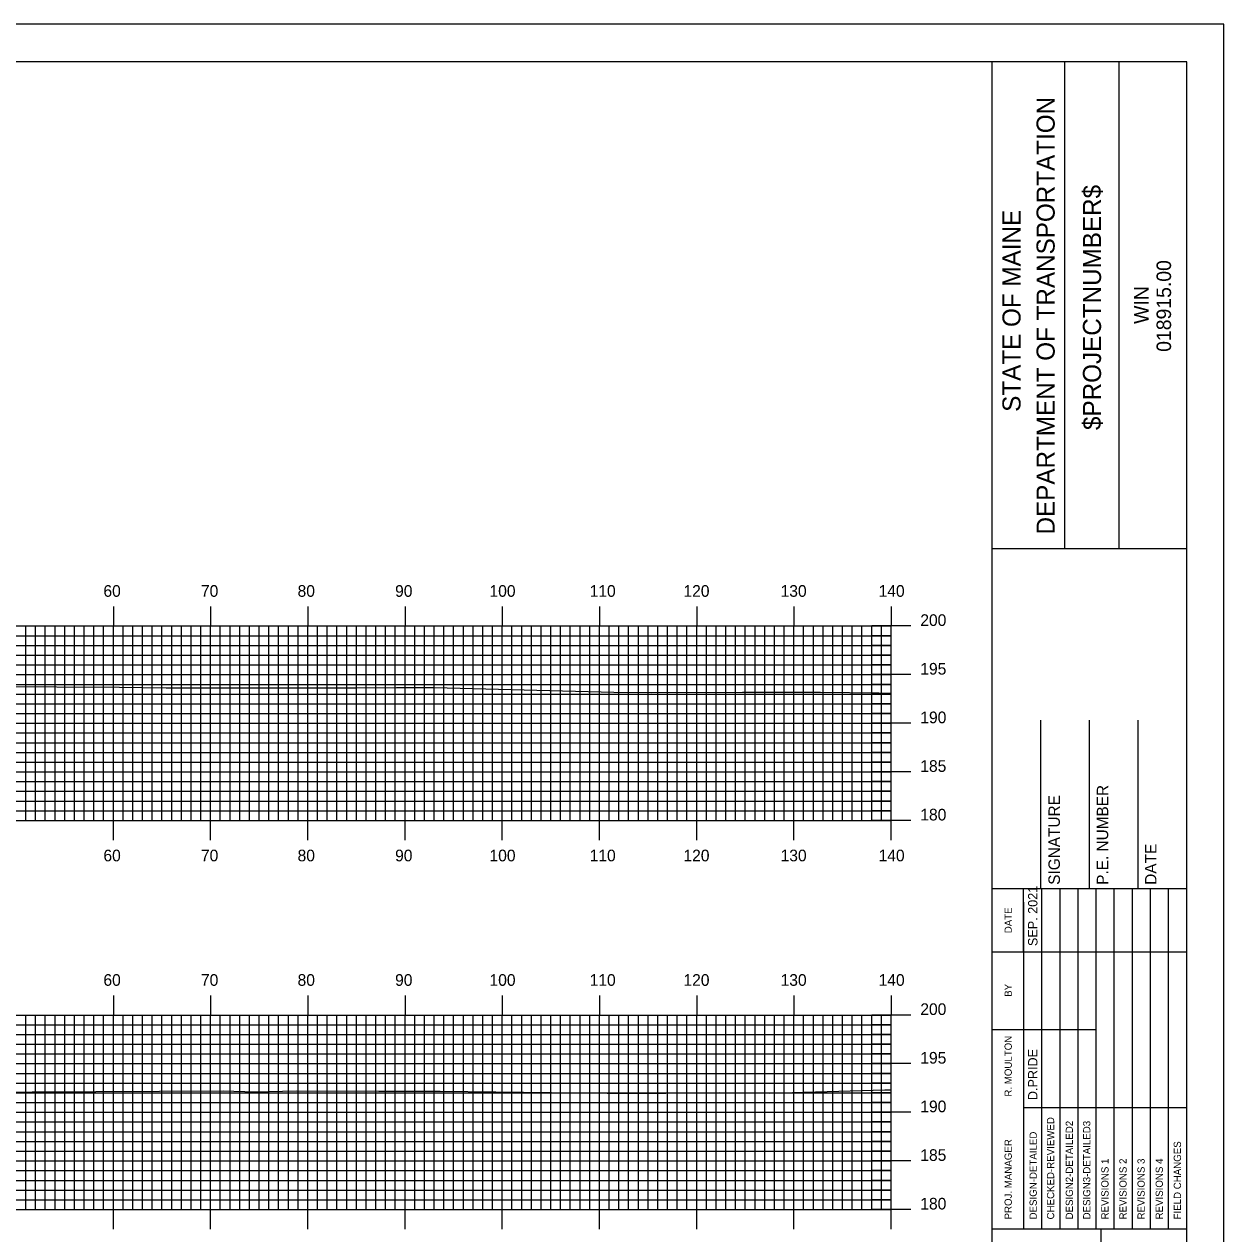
# Model space of a CAD drawing. Extents: x 1798781 to 1799124, y 442591 to 442811.
# Drawn here: x 1798997.8 to 1799121.2, y 442686.2 to 442810.5 of the extents above; entities that cross this region are included whole.
import ezdxf

# ---------------------------------------------------------------- set-up
doc = ezdxf.new("R2010")
doc.units = 0
for name, color, linetype in [('BORDER', 7, 'Continuous'), ('H_V ANNOTATION', 7, 'Continuous'), ('MAJOR', 7, 'Continuous'), ('MINOR', 7, 'Continuous'), ('PLOT BOUNDARY', 7, 'Continuous'), ('S_Roadway_Centerline', 7, 'Continuous')]:
    doc.layers.add(name, color=color, linetype=linetype)

msp = doc.modelspace()

# ---------------------------------------------------------------- linework, layer by layer
at = {"layer": 'BORDER'}
for p, q in [((1799097.38, 442596.67), (1799097.38, 442806.67)), ((1799104.84, 442756.66), (1799104.84, 442806.66)), ((1799110.43, 442756.66), (1799110.43, 442806.66)), ((1799097.39, 442756.65), (1799117.38, 442756.65)), ((1799102.38, 442721.67), (1799102.38, 442738.97)), ((1799107.38, 442721.67), (1799107.38, 442738.97)), ((1799112.38, 442721.67), (1799112.38, 442738.97)), ((1799097.38, 442721.67), (1799117.38, 442721.67)), ((1799097.38, 442686.67), (1799117.38, 442686.67)), ((1799108.57, 442616.67), (1799108.57, 442686.67))]:
    msp.add_line(p, q, dxfattribs=at)
msp.add_lwpolyline([(1798797.38, 442596.67), (1799117.38, 442596.67), (1799117.38, 442806.67), (1798797.38, 442806.67)], close=True, dxfattribs=at)
for points in [[(1799100.61, 442715.17), (1799100.61, 442721.67)], [(1799102.48, 442686.68), (1799102.48, 442721.67)], [(1799104.34, 442721.67), (1799104.34, 442686.68)], [(1799106.21, 442686.68), (1799106.21, 442721.67)], [(1799108.07, 442686.68), (1799108.07, 442721.67)], [(1799109.93, 442686.68), (1799109.93, 442721.67)], [(1799111.8, 442686.68), (1799111.8, 442721.67)], [(1799113.66, 442686.68), (1799113.66, 442721.67)], [(1799115.52, 442686.68), (1799115.52, 442721.67)], [(1799100.62, 442686.68), (1799100.62, 442720.26)], [(1799097.38, 442715.17), (1799117.38, 442715.17)], [(1799097.38, 442707.17), (1799100.62, 442707.17)], [(1799100.61, 442707.17), (1799108.07, 442707.17)], [(1799100.61, 442699.17), (1799117.38, 442699.17)]]:
    msp.add_lwpolyline(points, dxfattribs=at)
at = {"layer": 'MAJOR'}
for p, q in [((1799006.98, 442750.67), (1799006.98, 442748.67)), ((1799016.98, 442750.67), (1799016.98, 442748.67)), ((1799026.98, 442750.67), (1799026.98, 442748.67)), ((1799036.98, 442750.67), (1799036.98, 442748.67)), ((1799046.98, 442750.67), (1799046.98, 442748.67)), ((1799056.98, 442750.67), (1799056.98, 442748.67)), ((1799066.98, 442750.67), (1799066.98, 442748.67)), ((1799076.98, 442750.67), (1799076.98, 442748.67)), ((1799086.98, 442750.67), (1799086.98, 442748.67)), ((1798806.98, 442748.67), (1799086.98, 442748.67)), ((1798806.98, 442748.67), (1799086.98, 442748.67)), ((1799006.98, 442728.67), (1799006.98, 442748.67)), ((1799016.98, 442728.67), (1799016.98, 442748.67)), ((1799026.98, 442728.67), (1799026.98, 442748.67)), ((1799036.98, 442728.67), (1799036.98, 442748.67)), ((1799046.98, 442728.67), (1799046.98, 442748.67)), ((1799056.98, 442728.67), (1799056.98, 442748.67)), ((1799066.98, 442728.67), (1799066.98, 442748.67)), ((1799076.98, 442728.67), (1799076.98, 442748.67)), ((1799088.99, 442748.67), (1799084.98, 442748.67)), ((1799086.98, 442728.67), (1799086.98, 442748.67)), ((1799086.98, 442728.67), (1799086.98, 442748.67)), ((1798806.98, 442743.67), (1799086.98, 442743.67)), ((1799088.99, 442743.67), (1799084.98, 442743.67)), ((1798806.98, 442738.67), (1799086.98, 442738.67)), ((1799088.99, 442738.67), (1799084.98, 442738.67)), ((1798806.98, 442733.67), (1799086.98, 442733.67)), ((1799088.99, 442733.67), (1799084.98, 442733.67)), ((1798806.98, 442728.67), (1799086.98, 442728.67)), ((1798806.98, 442728.67), (1799086.98, 442728.67)), ((1799006.98, 442726.66), (1799006.98, 442728.67)), ((1799016.98, 442726.66), (1799016.98, 442728.67)), ((1799026.98, 442726.66), (1799026.98, 442728.67)), ((1799036.98, 442726.66), (1799036.98, 442728.67)), ((1799046.98, 442726.66), (1799046.98, 442728.67)), ((1799056.98, 442726.66), (1799056.98, 442728.67)), ((1799066.98, 442726.66), (1799066.98, 442728.67)), ((1799076.98, 442726.66), (1799076.98, 442728.67)), ((1799088.99, 442728.67), (1799084.98, 442728.67)), ((1799086.98, 442726.66), (1799086.98, 442728.67)), ((1799006.98, 442710.67), (1799006.98, 442708.67)), ((1799016.98, 442710.67), (1799016.98, 442708.67)), ((1799026.98, 442710.67), (1799026.98, 442708.67)), ((1799036.98, 442710.67), (1799036.98, 442708.67)), ((1799046.98, 442710.67), (1799046.98, 442708.67)), ((1799056.98, 442710.67), (1799056.98, 442708.67)), ((1799066.98, 442710.67), (1799066.98, 442708.67)), ((1799076.98, 442710.67), (1799076.98, 442708.67)), ((1799086.98, 442710.67), (1799086.98, 442708.67)), ((1798806.98, 442708.67), (1799086.98, 442708.67)), ((1798806.98, 442708.67), (1799086.98, 442708.67)), ((1799006.98, 442688.67), (1799006.98, 442708.67)), ((1799016.98, 442688.67), (1799016.98, 442708.67)), ((1799026.98, 442688.67), (1799026.98, 442708.67)), ((1799036.98, 442688.67), (1799036.98, 442708.67)), ((1799046.98, 442688.67), (1799046.98, 442708.67)), ((1799056.98, 442688.67), (1799056.98, 442708.67)), ((1799066.98, 442688.67), (1799066.98, 442708.67)), ((1799076.98, 442688.67), (1799076.98, 442708.67)), ((1799088.99, 442708.67), (1799084.98, 442708.67)), ((1799086.98, 442688.67), (1799086.98, 442708.67)), ((1799086.98, 442688.67), (1799086.98, 442708.67)), ((1798806.98, 442703.67), (1799086.98, 442703.67)), ((1799088.99, 442703.67), (1799084.98, 442703.67)), ((1798806.98, 442698.67), (1799086.98, 442698.67)), ((1799088.99, 442698.67), (1799084.98, 442698.67)), ((1798806.98, 442693.67), (1799086.98, 442693.67)), ((1799088.99, 442693.67), (1799084.98, 442693.67)), ((1798806.98, 442688.67), (1799086.98, 442688.67)), ((1798806.98, 442688.67), (1799086.98, 442688.67)), ((1799006.98, 442686.66), (1799006.98, 442688.67)), ((1799016.98, 442686.66), (1799016.98, 442688.67)), ((1799026.98, 442686.66), (1799026.98, 442688.67)), ((1799036.98, 442686.66), (1799036.98, 442688.67)), ((1799046.98, 442686.66), (1799046.98, 442688.67)), ((1799056.98, 442686.66), (1799056.98, 442688.67)), ((1799066.98, 442686.66), (1799066.98, 442688.67)), ((1799076.98, 442686.66), (1799076.98, 442688.67)), ((1799088.99, 442688.67), (1799084.98, 442688.67)), ((1799086.98, 442686.66), (1799086.98, 442688.67))]:
    msp.add_line(p, q, dxfattribs=at)
at = {"layer": 'MINOR'}
for p, q in [((1798997.98, 442728.67), (1798997.98, 442748.67)), ((1798998.98, 442728.67), (1798998.98, 442748.67)), ((1798999.98, 442728.67), (1798999.98, 442748.67)), ((1799000.98, 442728.67), (1799000.98, 442748.67)), ((1799001.98, 442728.67), (1799001.98, 442748.67)), ((1799002.98, 442728.67), (1799002.98, 442748.67)), ((1799003.98, 442728.67), (1799003.98, 442748.67)), ((1799004.98, 442728.67), (1799004.98, 442748.67)), ((1799005.98, 442728.67), (1799005.98, 442748.67)), ((1799007.98, 442728.67), (1799007.98, 442748.67)), ((1799008.98, 442728.67), (1799008.98, 442748.67)), ((1799009.98, 442728.67), (1799009.98, 442748.67)), ((1799010.98, 442728.67), (1799010.98, 442748.67)), ((1799011.98, 442728.67), (1799011.98, 442748.67)), ((1799012.98, 442728.67), (1799012.98, 442748.67)), ((1799013.98, 442728.67), (1799013.98, 442748.67)), ((1799014.98, 442728.67), (1799014.98, 442748.67)), ((1799015.98, 442728.67), (1799015.98, 442748.67)), ((1799017.98, 442728.67), (1799017.98, 442748.67)), ((1799018.98, 442728.67), (1799018.98, 442748.67)), ((1799019.98, 442728.67), (1799019.98, 442748.67)), ((1799020.98, 442728.67), (1799020.98, 442748.67)), ((1799021.98, 442728.67), (1799021.98, 442748.67)), ((1799022.98, 442728.67), (1799022.98, 442748.67)), ((1799023.98, 442728.67), (1799023.98, 442748.67)), ((1799024.98, 442728.67), (1799024.98, 442748.67)), ((1799025.98, 442728.67), (1799025.98, 442748.67)), ((1799027.98, 442728.67), (1799027.98, 442748.67)), ((1799028.98, 442728.67), (1799028.98, 442748.67)), ((1799029.98, 442728.67), (1799029.98, 442748.67)), ((1799030.98, 442728.67), (1799030.98, 442748.67)), ((1799031.98, 442728.67), (1799031.98, 442748.67)), ((1799032.98, 442728.67), (1799032.98, 442748.67)), ((1799033.98, 442728.67), (1799033.98, 442748.67)), ((1799034.98, 442728.67), (1799034.98, 442748.67)), ((1799035.98, 442728.67), (1799035.98, 442748.67)), ((1799037.98, 442728.67), (1799037.98, 442748.67)), ((1799038.98, 442728.67), (1799038.98, 442748.67)), ((1799039.98, 442728.67), (1799039.98, 442748.67)), ((1799040.98, 442728.67), (1799040.98, 442748.67)), ((1799041.98, 442728.67), (1799041.98, 442748.67)), ((1799042.98, 442728.67), (1799042.98, 442748.67)), ((1799043.98, 442728.67), (1799043.98, 442748.67)), ((1799044.98, 442728.67), (1799044.98, 442748.67)), ((1799045.98, 442728.67), (1799045.98, 442748.67)), ((1799047.98, 442728.67), (1799047.98, 442748.67)), ((1799048.98, 442728.67), (1799048.98, 442748.67)), ((1799049.98, 442728.67), (1799049.98, 442748.67)), ((1799050.98, 442728.67), (1799050.98, 442748.67)), ((1799051.98, 442728.67), (1799051.98, 442748.67)), ((1799052.98, 442728.67), (1799052.98, 442748.67)), ((1799053.98, 442728.67), (1799053.98, 442748.67)), ((1799054.98, 442728.67), (1799054.98, 442748.67)), ((1799055.98, 442728.67), (1799055.98, 442748.67)), ((1799057.98, 442728.67), (1799057.98, 442748.67)), ((1799058.98, 442728.67), (1799058.98, 442748.67)), ((1799059.98, 442728.67), (1799059.98, 442748.67)), ((1799060.98, 442728.67), (1799060.98, 442748.67)), ((1799061.98, 442728.67), (1799061.98, 442748.67)), ((1799062.98, 442728.67), (1799062.98, 442748.67)), ((1799063.98, 442728.67), (1799063.98, 442748.67)), ((1799064.98, 442728.67), (1799064.98, 442748.67)), ((1799065.98, 442728.67), (1799065.98, 442748.67)), ((1799067.98, 442728.67), (1799067.98, 442748.67)), ((1799068.98, 442728.67), (1799068.98, 442748.67)), ((1799069.98, 442728.67), (1799069.98, 442748.67)), ((1799070.98, 442728.67), (1799070.98, 442748.67)), ((1799071.98, 442728.67), (1799071.98, 442748.67)), ((1799072.98, 442728.67), (1799072.98, 442748.67)), ((1799073.98, 442728.67), (1799073.98, 442748.67)), ((1799074.98, 442728.67), (1799074.98, 442748.67)), ((1799075.98, 442728.67), (1799075.98, 442748.67)), ((1799077.98, 442728.67), (1799077.98, 442748.67)), ((1799078.98, 442728.67), (1799078.98, 442748.67)), ((1799079.98, 442728.67), (1799079.98, 442748.67)), ((1799080.98, 442728.67), (1799080.98, 442748.67)), ((1799081.98, 442728.67), (1799081.98, 442748.67)), ((1799082.98, 442728.67), (1799082.98, 442748.67)), ((1799083.98, 442728.67), (1799083.98, 442748.67)), ((1799084.98, 442728.67), (1799084.98, 442748.67)), ((1799085.98, 442728.67), (1799085.98, 442748.67)), ((1798806.98, 442747.67), (1799086.98, 442747.67)), ((1799086.98, 442747.67), (1799084.98, 442747.67)), ((1798806.98, 442746.67), (1799086.98, 442746.67)), ((1798806.98, 442745.67), (1799086.98, 442745.67)), ((1799086.98, 442746.67), (1799084.98, 442746.67)), ((1799086.98, 442745.67), (1799084.98, 442745.67)), ((1798806.98, 442744.67), (1799086.98, 442744.67)), ((1799086.98, 442744.67), (1799084.98, 442744.67)), ((1798806.98, 442742.67), (1799086.98, 442742.67)), ((1799086.98, 442742.67), (1799084.98, 442742.67)), ((1798806.98, 442741.67), (1799086.98, 442741.67)), ((1798806.98, 442740.67), (1799086.98, 442740.67)), ((1799086.98, 442741.67), (1799084.98, 442741.67)), ((1799086.98, 442740.67), (1799084.98, 442740.67)), ((1798806.98, 442739.67), (1799086.98, 442739.67)), ((1799086.98, 442739.67), (1799084.98, 442739.67)), ((1798806.98, 442737.67), (1799086.98, 442737.67)), ((1799086.98, 442737.67), (1799084.98, 442737.67)), ((1798806.98, 442736.67), (1799086.98, 442736.67)), ((1798806.98, 442735.67), (1799086.98, 442735.67)), ((1799086.98, 442736.67), (1799084.98, 442736.67)), ((1799086.98, 442735.67), (1799084.98, 442735.67)), ((1798806.98, 442734.67), (1799086.98, 442734.67)), ((1799086.98, 442734.67), (1799084.98, 442734.67)), ((1798806.98, 442732.67), (1799086.98, 442732.67)), ((1799086.98, 442732.67), (1799084.98, 442732.67)), ((1798806.98, 442731.67), (1799086.98, 442731.67)), ((1798806.98, 442730.67), (1799086.98, 442730.67)), ((1799086.98, 442731.67), (1799084.98, 442731.67)), ((1799086.98, 442730.67), (1799084.98, 442730.67)), ((1798806.98, 442729.67), (1799086.98, 442729.67)), ((1799086.98, 442729.67), (1799084.98, 442729.67)), ((1798997.98, 442688.67), (1798997.98, 442708.67)), ((1798998.98, 442688.67), (1798998.98, 442708.67)), ((1798999.98, 442688.67), (1798999.98, 442708.67)), ((1799000.98, 442688.67), (1799000.98, 442708.67)), ((1799001.98, 442688.67), (1799001.98, 442708.67)), ((1799002.98, 442688.67), (1799002.98, 442708.67)), ((1799003.98, 442688.67), (1799003.98, 442708.67)), ((1799004.98, 442688.67), (1799004.98, 442708.67)), ((1799005.98, 442688.67), (1799005.98, 442708.67)), ((1799007.98, 442688.67), (1799007.98, 442708.67)), ((1799008.98, 442688.67), (1799008.98, 442708.67)), ((1799009.98, 442688.67), (1799009.98, 442708.67)), ((1799010.98, 442688.67), (1799010.98, 442708.67)), ((1799011.98, 442688.67), (1799011.98, 442708.67)), ((1799012.98, 442688.67), (1799012.98, 442708.67)), ((1799013.98, 442688.67), (1799013.98, 442708.67)), ((1799014.98, 442688.67), (1799014.98, 442708.67)), ((1799015.98, 442688.67), (1799015.98, 442708.67)), ((1799017.98, 442688.67), (1799017.98, 442708.67)), ((1799018.98, 442688.67), (1799018.98, 442708.67)), ((1799019.98, 442688.67), (1799019.98, 442708.67)), ((1799020.98, 442688.67), (1799020.98, 442708.67)), ((1799021.98, 442688.67), (1799021.98, 442708.67)), ((1799022.98, 442688.67), (1799022.98, 442708.67)), ((1799023.98, 442688.67), (1799023.98, 442708.67)), ((1799024.98, 442688.67), (1799024.98, 442708.67)), ((1799025.98, 442688.67), (1799025.98, 442708.67)), ((1799027.98, 442688.67), (1799027.98, 442708.67)), ((1799028.98, 442688.67), (1799028.98, 442708.67)), ((1799029.98, 442688.67), (1799029.98, 442708.67)), ((1799030.98, 442688.67), (1799030.98, 442708.67)), ((1799031.98, 442688.67), (1799031.98, 442708.67)), ((1799032.98, 442688.67), (1799032.98, 442708.67)), ((1799033.98, 442688.67), (1799033.98, 442708.67)), ((1799034.98, 442688.67), (1799034.98, 442708.67)), ((1799035.98, 442688.67), (1799035.98, 442708.67)), ((1799037.98, 442688.67), (1799037.98, 442708.67)), ((1799038.98, 442688.67), (1799038.98, 442708.67)), ((1799039.98, 442688.67), (1799039.98, 442708.67)), ((1799040.98, 442688.67), (1799040.98, 442708.67)), ((1799041.98, 442688.67), (1799041.98, 442708.67)), ((1799042.98, 442688.67), (1799042.98, 442708.67)), ((1799043.98, 442688.67), (1799043.98, 442708.67)), ((1799044.98, 442688.67), (1799044.98, 442708.67)), ((1799045.98, 442688.67), (1799045.98, 442708.67)), ((1799047.98, 442688.67), (1799047.98, 442708.67)), ((1799048.98, 442688.67), (1799048.98, 442708.67)), ((1799049.98, 442688.67), (1799049.98, 442708.67)), ((1799050.98, 442688.67), (1799050.98, 442708.67)), ((1799051.98, 442688.67), (1799051.98, 442708.67)), ((1799052.98, 442688.67), (1799052.98, 442708.67)), ((1799053.98, 442688.67), (1799053.98, 442708.67)), ((1799054.98, 442688.67), (1799054.98, 442708.67)), ((1799055.98, 442688.67), (1799055.98, 442708.67)), ((1799057.98, 442688.67), (1799057.98, 442708.67)), ((1799058.98, 442688.67), (1799058.98, 442708.67)), ((1799059.98, 442688.67), (1799059.98, 442708.67)), ((1799060.98, 442688.67), (1799060.98, 442708.67)), ((1799061.98, 442688.67), (1799061.98, 442708.67)), ((1799062.98, 442688.67), (1799062.98, 442708.67)), ((1799063.98, 442688.67), (1799063.98, 442708.67)), ((1799064.98, 442688.67), (1799064.98, 442708.67)), ((1799065.98, 442688.67), (1799065.98, 442708.67)), ((1799067.98, 442688.67), (1799067.98, 442708.67)), ((1799068.98, 442688.67), (1799068.98, 442708.67)), ((1799069.98, 442688.67), (1799069.98, 442708.67)), ((1799070.98, 442688.67), (1799070.98, 442708.67)), ((1799071.98, 442688.67), (1799071.98, 442708.67)), ((1799072.98, 442688.67), (1799072.98, 442708.67)), ((1799073.98, 442688.67), (1799073.98, 442708.67)), ((1799074.98, 442688.67), (1799074.98, 442708.67)), ((1799075.98, 442688.67), (1799075.98, 442708.67)), ((1799077.98, 442688.67), (1799077.98, 442708.67)), ((1799078.98, 442688.67), (1799078.98, 442708.67)), ((1799079.98, 442688.67), (1799079.98, 442708.67)), ((1799080.98, 442688.67), (1799080.98, 442708.67)), ((1799081.98, 442688.67), (1799081.98, 442708.67)), ((1799082.98, 442688.67), (1799082.98, 442708.67)), ((1799083.98, 442688.67), (1799083.98, 442708.67)), ((1799084.98, 442688.67), (1799084.98, 442708.67)), ((1799085.98, 442688.67), (1799085.98, 442708.67)), ((1798806.98, 442707.67), (1799086.98, 442707.67)), ((1799086.98, 442707.67), (1799084.98, 442707.67)), ((1798806.98, 442706.67), (1799086.98, 442706.67)), ((1799086.98, 442706.67), (1799084.98, 442706.67)), ((1798806.98, 442705.67), (1799086.98, 442705.67)), ((1798806.98, 442704.67), (1799086.98, 442704.67)), ((1799086.98, 442705.67), (1799084.98, 442705.67)), ((1799086.98, 442704.67), (1799084.98, 442704.67)), ((1798806.98, 442702.67), (1799086.98, 442702.67)), ((1799086.98, 442702.67), (1799084.98, 442702.67)), ((1798806.98, 442701.67), (1799086.98, 442701.67)), ((1799086.98, 442701.67), (1799084.98, 442701.67)), ((1798806.98, 442700.67), (1799086.98, 442700.67)), ((1798806.98, 442699.67), (1799086.98, 442699.67)), ((1799086.98, 442700.67), (1799084.98, 442700.67)), ((1799086.98, 442699.67), (1799084.98, 442699.67)), ((1798806.98, 442697.67), (1799086.98, 442697.67)), ((1799086.98, 442697.67), (1799084.98, 442697.67)), ((1798806.98, 442696.67), (1799086.98, 442696.67)), ((1799086.98, 442696.67), (1799084.98, 442696.67)), ((1798806.98, 442695.67), (1799086.98, 442695.67)), ((1798806.98, 442694.67), (1799086.98, 442694.67)), ((1799086.98, 442695.67), (1799084.98, 442695.67)), ((1799086.98, 442694.67), (1799084.98, 442694.67)), ((1798806.98, 442692.67), (1799086.98, 442692.67)), ((1799086.98, 442692.67), (1799084.98, 442692.67)), ((1798806.98, 442691.67), (1799086.98, 442691.67)), ((1799086.98, 442691.67), (1799084.98, 442691.67)), ((1798806.98, 442690.67), (1799086.98, 442690.67)), ((1798806.98, 442689.67), (1799086.98, 442689.67)), ((1799086.98, 442690.67), (1799084.98, 442690.67)), ((1799086.98, 442689.67), (1799084.98, 442689.67))]:
    msp.add_line(p, q, dxfattribs=at)
at = {"layer": 'PLOT BOUNDARY'}
msp.add_lwpolyline([(1798781.2, 442590.55), (1799121.2, 442590.55), (1799121.2, 442810.55), (1798781.2, 442810.55)], close=True, dxfattribs=at)
at = {"layer": 'S_Roadway_Centerline'}
for points in [[(1798994.67, 442742.45), (1799007.61, 442742.39), (1799012.43, 442742.3), (1799031.95, 442742.32), (1799036.09, 442742.35), (1799040, 442742.34), (1799058.45, 442741.88), (1799062.29, 442741.83), (1799071.69, 442741.85), (1799079.71, 442741.86), (1799085.73, 442741.78), (1799086.98, 442741.75)], [(1798996.53, 442700.72), (1798998.64, 442700.76), (1799018.27, 442700.86), (1799021.59, 442700.78), (1799025.77, 442700.87), (1799034.3, 442700.85), (1799040.6, 442700.83), (1799057.76, 442700.65), (1799063.8, 442700.63), (1799069.35, 442700.69), (1799074.46, 442700.63), (1799086.34, 442700.96), (1799086.98, 442700.98)]]:
    msp.add_lwpolyline(points, dxfattribs=at)

# ---------------------------------------------------------------- texts
at = {"layer": 'BORDER'}
for s, height, p in [('DEPARTMENT OF TRANSPORTATION', 1.8635, (1799103.8, 442758.08)), ('$PROJECTNUMBER$', 1.8635, (1799108.57, 442768.82)), ('STATE OF MAINE', 1.8635, (1799100.29, 442770.69)), ('018915.00', 1.491, (1799115.77, 442776.86)), ('WIN', 1.491, (1799113.46, 442779.73)), ('P.E. NUMBER', 1.1811, (1799109.31, 442722.06)), ('SIGNATURE', 1.181, (1799104.34, 442722.06)), ('DATE', 1.181, (1799114.27, 442722.06)), ('SEP. 2021', 0.969, (1799102.03, 442715.76)), ('DATE', 0.743, (1799099.39, 442717.08)), ('BY', 0.743, (1799099.39, 442710.54)), ('R. MOULTON', 0.745, (1799099.39, 442700.28)), ('D.PRIDE', 0.969, (1799102.03, 442699.92)), ('CHECKED-REVIEWED', 0.7455, (1799103.75, 442687.65)), ('DESIGN2-DETAILED2', 0.7455, (1799105.68, 442687.65)), ('DESIGN3-DETAILED3', 0.7455, (1799107.47, 442687.65)), ('PROJ. MANAGER', 0.7455, (1799099.39, 442687.65)), ('DESIGN-DETAILED', 0.7455, (1799101.96, 442687.65)), ('FIELD CHANGES', 0.7455, (1799116.79, 442687.65)), ('REVISIONS 1', 0.7455, (1799109.34, 442687.65)), ('REVISIONS 2', 0.7455, (1799111.2, 442687.65)), ('REVISIONS 3', 0.7455, (1799113.06, 442687.65)), ('REVISIONS 4', 0.7455, (1799114.93, 442687.65))]:
    msp.add_text(s, height=height, rotation=90, dxfattribs=at).set_placement(p)
at = {"layer": 'H_V ANNOTATION'}
for s, p in [('60', (1799005.96, 442751.67)), ('70', (1799015.99, 442751.67)), ('80', (1799025.93, 442751.67)), ('90', (1799035.96, 442751.67)), ('100', (1799045.67, 442751.67)), ('110', (1799055.97, 442751.67)), ('120', (1799065.62, 442751.67)), ('130', (1799075.61, 442751.67)), ('140', (1799085.69, 442751.67)), ('200', (1799089.98, 442748.67)), ('195', (1799089.98, 442743.67)), ('190', (1799089.98, 442738.67)), ('185', (1799089.98, 442733.67)), ('180', (1799089.98, 442728.67)), ('60', (1799005.96, 442724.47)), ('70', (1799015.99, 442724.47)), ('80', (1799025.93, 442724.47)), ('90', (1799035.96, 442724.47)), ('100', (1799045.67, 442724.47)), ('110', (1799055.97, 442724.47)), ('120', (1799065.62, 442724.47)), ('130', (1799075.61, 442724.47)), ('140', (1799085.69, 442724.47)), ('60', (1799005.96, 442711.67)), ('70', (1799015.99, 442711.67)), ('80', (1799025.93, 442711.67)), ('90', (1799035.96, 442711.67)), ('100', (1799045.67, 442711.67)), ('110', (1799055.97, 442711.67)), ('120', (1799065.62, 442711.67)), ('130', (1799075.61, 442711.67)), ('140', (1799085.69, 442711.67)), ('200', (1799089.98, 442708.67)), ('195', (1799089.98, 442703.67)), ('190', (1799089.98, 442698.67)), ('185', (1799089.98, 442693.67)), ('180', (1799089.98, 442688.67))]:
    msp.add_text(s, height=1.2, dxfattribs=at).set_placement(p)

doc.saveas('drawing.dxf')
